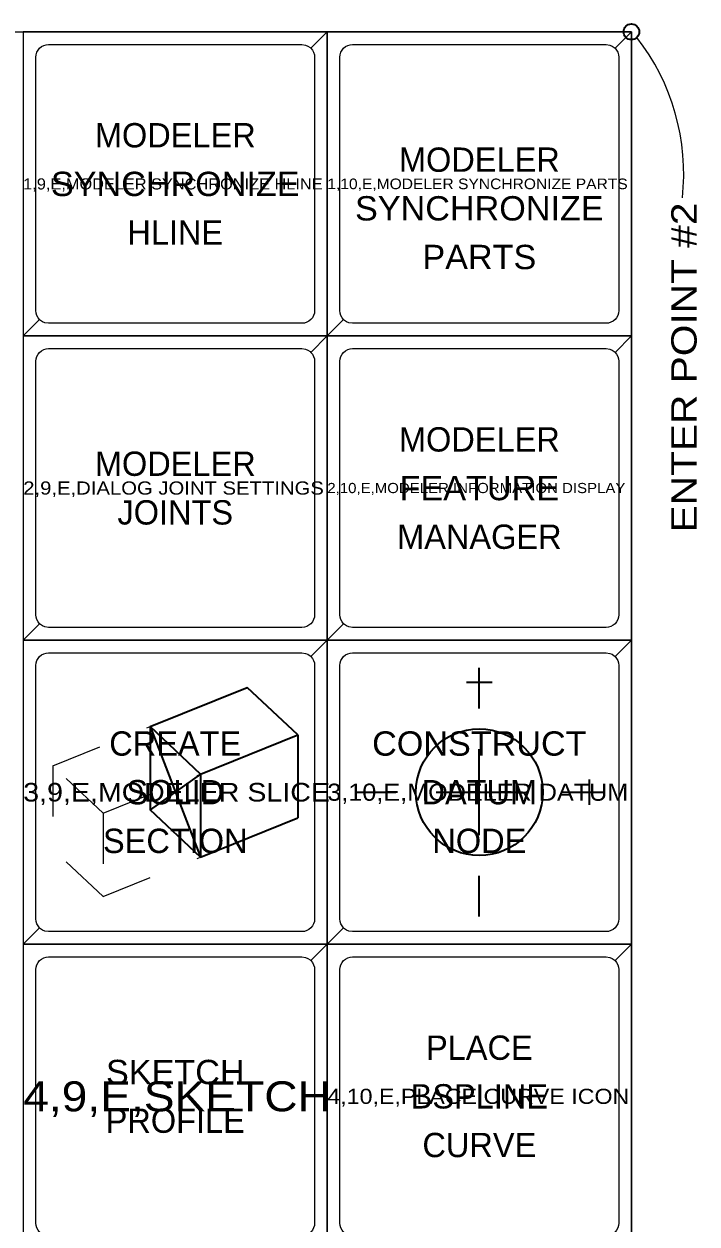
# Model space of a CAD drawing. Extents: x 95909.2 to 95923.3, y 90965 to 90971.2.
# Drawn here: x 95914.588 to 95915.916, y 90968.808 to 90971.176 of the extents above; entities that cross this region are included whole.
import ezdxf
from ezdxf.enums import TextEntityAlignment as Align

# ---------------------------------------------------------------- set-up
doc = ezdxf.new("R2010")
doc.units = 0
doc.header["$LTSCALE"] = 0.019
doc.linetypes.add('MEDIUM_DASHED', pattern=[4.5, 3, -1.5])
for name, color, linetype, lineweight in [('1', 7, 'Continuous', 25), ('10', 7, 'Continuous', 13), ('2', 7, 'Continuous', 25), ('3', 7, 'Continuous', 25), ('4', 7, 'Continuous', 25), ('6', 7, 'Continuous', 13), ('7', 7, 'Continuous', 35)]:
    doc.layers.add(name, color=color, linetype=linetype, lineweight=lineweight)
for name, color, linetype in [('5', 7, 'Continuous'), ('63', 7, 'Continuous'), ('9', 7, 'Continuous')]:
    doc.layers.add(name, color=color, linetype=linetype)

msp = doc.modelspace()

# ---------------------------------------------------------------- linework, layer by layer
at = {"layer": '1'}
for points in [[(95914.5868, 90970.5603), (95915.1868, 90970.5603), (95915.1868, 90971.1603), (95914.5868, 90971.1603)], [(95915.1868, 90970.5603), (95915.7868, 90970.5603), (95915.7868, 90971.1603), (95915.1868, 90971.1603)], [(95914.5868, 90969.9603), (95915.1868, 90969.9603), (95915.1868, 90970.5603), (95914.5868, 90970.5603)], [(95915.1868, 90969.9603), (95915.7868, 90969.9603), (95915.7868, 90970.5603), (95915.1868, 90970.5603)], [(95914.5868, 90969.3603), (95915.1868, 90969.3603), (95915.1868, 90969.9603), (95914.5868, 90969.9603)], [(95915.1868, 90969.3603), (95915.7868, 90969.3603), (95915.7868, 90969.9603), (95915.1868, 90969.9603)], [(95914.5868, 90968.7603), (95915.1868, 90968.7603), (95915.1868, 90969.3603), (95914.5868, 90969.3603)], [(95915.1868, 90968.7603), (95915.7868, 90968.7603), (95915.7868, 90969.3603), (95915.1868, 90969.3603)]]:
    msp.add_lwpolyline(points, close=True, dxfattribs=at)
at = {"layer": '10'}
msp.add_lwpolyline([(95909.7868, 90971.1603), (95915.7868, 90971.1603), (95915.7868, 90966.3603), (95909.7868, 90966.3603)], close=True, dxfattribs=at)
at = {"layer": '2'}
for points in [[(95914.5868, 90970.5603), (95915.1868, 90970.5603), (95915.1868, 90971.1603), (95914.5868, 90971.1603)], [(95915.1868, 90970.5603), (95915.7868, 90970.5603), (95915.7868, 90971.1603), (95915.1868, 90971.1603)], [(95914.5868, 90969.9603), (95915.1868, 90969.9603), (95915.1868, 90970.5603), (95914.5868, 90970.5603)], [(95915.1868, 90969.9603), (95915.7868, 90969.9603), (95915.7868, 90970.5603), (95915.1868, 90970.5603)], [(95914.5868, 90969.3603), (95915.1868, 90969.3603), (95915.1868, 90969.9603), (95914.5868, 90969.9603)], [(95915.1868, 90969.3603), (95915.7868, 90969.3603), (95915.7868, 90969.9603), (95915.1868, 90969.9603)], [(95914.5868, 90968.7603), (95915.1868, 90968.7603), (95915.1868, 90969.3603), (95914.5868, 90969.3603)], [(95915.1868, 90968.7603), (95915.7868, 90968.7603), (95915.7868, 90969.3603), (95915.1868, 90969.3603)]]:
    msp.add_lwpolyline(points, close=True, dxfattribs=at)
at = {"layer": '3'}
for points in [[(95915.1868, 90971.1603), (95914.5868, 90971.1603), (95914.5868, 90970.5603), (95914.6191, 90970.5926), (95914.616, 90970.5964), (95914.6137, 90970.6007), (95914.6123, 90970.6054), (95914.6118, 90970.6103), (95914.6118, 90971.1103), (95914.6123, 90971.1152), (95914.6137, 90971.1199), (95914.616, 90971.1242), (95914.6191, 90971.128), (95914.6191, 90971.128), (95914.6229, 90971.1311), (95914.6272, 90971.1334), (95914.6319, 90971.1348), (95914.6368, 90971.1353), (95915.1368, 90971.1353), (95915.1441, 90971.1342), (95915.1486, 90971.1323), (95915.1527, 90971.1296), (95915.1545, 90971.128)], [(95915.7868, 90971.1603), (95915.1868, 90971.1603), (95915.1868, 90970.5603), (95915.2191, 90970.5926), (95915.216, 90970.5964), (95915.2137, 90970.6007), (95915.2123, 90970.6054), (95915.2118, 90970.6103), (95915.2118, 90971.1103), (95915.2123, 90971.1152), (95915.2137, 90971.1199), (95915.216, 90971.1242), (95915.2191, 90971.128), (95915.2191, 90971.128), (95915.2229, 90971.1311), (95915.2272, 90971.1334), (95915.2319, 90971.1348), (95915.2368, 90971.1353), (95915.7368, 90971.1353), (95915.7441, 90971.1342), (95915.7486, 90971.1323), (95915.7527, 90971.1296), (95915.7545, 90971.128)], [(95915.1868, 90970.5603), (95914.5868, 90970.5603), (95914.5868, 90969.9603), (95914.6191, 90969.9926), (95914.616, 90969.9964), (95914.6137, 90970.0007), (95914.6123, 90970.0054), (95914.6118, 90970.0103), (95914.6118, 90970.5103), (95914.6123, 90970.5152), (95914.6137, 90970.5199), (95914.616, 90970.5242), (95914.6191, 90970.528), (95914.6191, 90970.528), (95914.6229, 90970.5311), (95914.6272, 90970.5334), (95914.6319, 90970.5348), (95914.6368, 90970.5353), (95915.1368, 90970.5353), (95915.1441, 90970.5342), (95915.1486, 90970.5323), (95915.1527, 90970.5296), (95915.1545, 90970.528)], [(95915.7868, 90970.5603), (95915.1868, 90970.5603), (95915.1868, 90969.9603), (95915.2191, 90969.9926), (95915.216, 90969.9964), (95915.2137, 90970.0007), (95915.2123, 90970.0054), (95915.2118, 90970.0103), (95915.2118, 90970.5103), (95915.2123, 90970.5152), (95915.2137, 90970.5199), (95915.216, 90970.5242), (95915.2191, 90970.528), (95915.2191, 90970.528), (95915.2229, 90970.5311), (95915.2272, 90970.5334), (95915.2319, 90970.5348), (95915.2368, 90970.5353), (95915.7368, 90970.5353), (95915.7441, 90970.5342), (95915.7486, 90970.5323), (95915.7527, 90970.5296), (95915.7545, 90970.528)], [(95915.1868, 90969.9603), (95914.5868, 90969.9603), (95914.5868, 90969.3603), (95914.6191, 90969.3926), (95914.616, 90969.3964), (95914.6137, 90969.4007), (95914.6123, 90969.4054), (95914.6118, 90969.4103), (95914.6118, 90969.9103), (95914.6123, 90969.9152), (95914.6137, 90969.9199), (95914.616, 90969.9242), (95914.6191, 90969.928), (95914.6191, 90969.928), (95914.6229, 90969.9311), (95914.6272, 90969.9334), (95914.6319, 90969.9348), (95914.6368, 90969.9353), (95915.1368, 90969.9353), (95915.1441, 90969.9342), (95915.1486, 90969.9323), (95915.1527, 90969.9296), (95915.1545, 90969.928)], [(95915.7868, 90969.9603), (95915.1868, 90969.9603), (95915.1868, 90969.3603), (95915.2191, 90969.3926), (95915.216, 90969.3964), (95915.2137, 90969.4007), (95915.2123, 90969.4054), (95915.2118, 90969.4103), (95915.2118, 90969.9103), (95915.2123, 90969.9152), (95915.2137, 90969.9199), (95915.216, 90969.9242), (95915.2191, 90969.928), (95915.2191, 90969.928), (95915.2229, 90969.9311), (95915.2272, 90969.9334), (95915.2319, 90969.9348), (95915.2368, 90969.9353), (95915.7368, 90969.9353), (95915.7441, 90969.9342), (95915.7486, 90969.9323), (95915.7527, 90969.9296), (95915.7545, 90969.928)], [(95915.1868, 90969.3603), (95914.5868, 90969.3603), (95914.5868, 90968.7603), (95914.6191, 90968.7926), (95914.616, 90968.7964), (95914.6137, 90968.8007), (95914.6123, 90968.8054), (95914.6118, 90968.8103), (95914.6118, 90969.3103), (95914.6123, 90969.3152), (95914.6137, 90969.3199), (95914.616, 90969.3242), (95914.6191, 90969.328), (95914.6191, 90969.328), (95914.6229, 90969.3311), (95914.6272, 90969.3334), (95914.6319, 90969.3348), (95914.6368, 90969.3353), (95915.1368, 90969.3353), (95915.1441, 90969.3342), (95915.1486, 90969.3323), (95915.1527, 90969.3296), (95915.1545, 90969.328)], [(95915.7868, 90969.3603), (95915.1868, 90969.3603), (95915.1868, 90968.7603), (95915.2191, 90968.7926), (95915.216, 90968.7964), (95915.2137, 90968.8007), (95915.2123, 90968.8054), (95915.2118, 90968.8103), (95915.2118, 90969.3103), (95915.2123, 90969.3152), (95915.2137, 90969.3199), (95915.216, 90969.3242), (95915.2191, 90969.328), (95915.2191, 90969.328), (95915.2229, 90969.3311), (95915.2272, 90969.3334), (95915.2319, 90969.3348), (95915.2368, 90969.3353), (95915.7368, 90969.3353), (95915.7441, 90969.3342), (95915.7486, 90969.3323), (95915.7527, 90969.3296), (95915.7545, 90969.328)]]:
    msp.add_lwpolyline(points, close=True, dxfattribs=at)
at = {"layer": '4'}
for points in [[(95914.5868, 90970.5603), (95915.1868, 90970.5603), (95915.1868, 90971.1603), (95915.1545, 90971.128), (95915.1576, 90971.1242), (95915.1599, 90971.1199), (95915.1613, 90971.1152), (95915.1618, 90971.1103), (95915.1618, 90970.6103), (95915.1613, 90970.6054), (95915.1599, 90970.6007), (95915.1576, 90970.5964), (95915.1545, 90970.5926), (95915.1545, 90970.5926), (95915.1507, 90970.5895), (95915.1464, 90970.5872), (95915.1417, 90970.5858), (95915.1368, 90970.5853), (95914.6368, 90970.5853), (95914.6295, 90970.5864), (95914.625, 90970.5883), (95914.6209, 90970.591), (95914.6191, 90970.5926)], [(95915.1868, 90970.5603), (95915.7868, 90970.5603), (95915.7868, 90971.1603), (95915.7545, 90971.128), (95915.7576, 90971.1242), (95915.7599, 90971.1199), (95915.7613, 90971.1152), (95915.7618, 90971.1103), (95915.7618, 90970.6103), (95915.7613, 90970.6054), (95915.7599, 90970.6007), (95915.7576, 90970.5964), (95915.7545, 90970.5926), (95915.7545, 90970.5926), (95915.7507, 90970.5895), (95915.7464, 90970.5872), (95915.7417, 90970.5858), (95915.7368, 90970.5853), (95915.2368, 90970.5853), (95915.2295, 90970.5864), (95915.225, 90970.5883), (95915.2209, 90970.591), (95915.2191, 90970.5926)], [(95914.5868, 90969.9603), (95915.1868, 90969.9603), (95915.1868, 90970.5603), (95915.1545, 90970.528), (95915.1576, 90970.5242), (95915.1599, 90970.5199), (95915.1613, 90970.5152), (95915.1618, 90970.5103), (95915.1618, 90970.0103), (95915.1613, 90970.0054), (95915.1599, 90970.0007), (95915.1576, 90969.9964), (95915.1545, 90969.9926), (95915.1545, 90969.9926), (95915.1507, 90969.9895), (95915.1464, 90969.9872), (95915.1417, 90969.9858), (95915.1368, 90969.9853), (95914.6368, 90969.9853), (95914.6295, 90969.9864), (95914.625, 90969.9883), (95914.6209, 90969.991), (95914.6191, 90969.9926)], [(95915.1868, 90969.9603), (95915.7868, 90969.9603), (95915.7868, 90970.5603), (95915.7545, 90970.528), (95915.7576, 90970.5242), (95915.7599, 90970.5199), (95915.7613, 90970.5152), (95915.7618, 90970.5103), (95915.7618, 90970.0103), (95915.7613, 90970.0054), (95915.7599, 90970.0007), (95915.7576, 90969.9964), (95915.7545, 90969.9926), (95915.7545, 90969.9926), (95915.7507, 90969.9895), (95915.7464, 90969.9872), (95915.7417, 90969.9858), (95915.7368, 90969.9853), (95915.2368, 90969.9853), (95915.2295, 90969.9864), (95915.225, 90969.9883), (95915.2209, 90969.991), (95915.2191, 90969.9926)], [(95914.5868, 90969.3603), (95915.1868, 90969.3603), (95915.1868, 90969.9603), (95915.1545, 90969.928), (95915.1576, 90969.9242), (95915.1599, 90969.9199), (95915.1613, 90969.9152), (95915.1618, 90969.9103), (95915.1618, 90969.4103), (95915.1613, 90969.4054), (95915.1599, 90969.4007), (95915.1576, 90969.3964), (95915.1545, 90969.3926), (95915.1545, 90969.3926), (95915.1507, 90969.3895), (95915.1464, 90969.3872), (95915.1417, 90969.3858), (95915.1368, 90969.3853), (95914.6368, 90969.3853), (95914.6295, 90969.3864), (95914.625, 90969.3883), (95914.6209, 90969.391), (95914.6191, 90969.3926)], [(95915.1868, 90969.3603), (95915.7868, 90969.3603), (95915.7868, 90969.9603), (95915.7545, 90969.928), (95915.7576, 90969.9242), (95915.7599, 90969.9199), (95915.7613, 90969.9152), (95915.7618, 90969.9103), (95915.7618, 90969.4103), (95915.7613, 90969.4054), (95915.7599, 90969.4007), (95915.7576, 90969.3964), (95915.7545, 90969.3926), (95915.7545, 90969.3926), (95915.7507, 90969.3895), (95915.7464, 90969.3872), (95915.7417, 90969.3858), (95915.7368, 90969.3853), (95915.2368, 90969.3853), (95915.2295, 90969.3864), (95915.225, 90969.3883), (95915.2209, 90969.391), (95915.2191, 90969.3926)], [(95914.5868, 90968.7603), (95915.1868, 90968.7603), (95915.1868, 90969.3603), (95915.1545, 90969.328), (95915.1576, 90969.3242), (95915.1599, 90969.3199), (95915.1613, 90969.3152), (95915.1618, 90969.3103), (95915.1618, 90968.8103), (95915.1613, 90968.8054), (95915.1599, 90968.8007), (95915.1576, 90968.7964), (95915.1545, 90968.7926), (95915.1545, 90968.7926), (95915.1507, 90968.7895), (95915.1464, 90968.7872), (95915.1417, 90968.7858), (95915.1368, 90968.7853), (95914.6368, 90968.7853), (95914.6295, 90968.7864), (95914.625, 90968.7883), (95914.6209, 90968.791), (95914.6191, 90968.7926)], [(95915.1868, 90968.7603), (95915.7868, 90968.7603), (95915.7868, 90969.3603), (95915.7545, 90969.328), (95915.7576, 90969.3242), (95915.7599, 90969.3199), (95915.7613, 90969.3152), (95915.7618, 90969.3103), (95915.7618, 90968.8103), (95915.7613, 90968.8054), (95915.7599, 90968.8007), (95915.7576, 90968.7964), (95915.7545, 90968.7926), (95915.7545, 90968.7926), (95915.7507, 90968.7895), (95915.7464, 90968.7872), (95915.7417, 90968.7858), (95915.7368, 90968.7853), (95915.2368, 90968.7853), (95915.2295, 90968.7864), (95915.225, 90968.7883), (95915.2209, 90968.791), (95915.2191, 90968.7926)]]:
    msp.add_lwpolyline(points, close=True, dxfattribs=at)
at = {"layer": '6', "lineweight": 35}
for p, q in [((95915.4868, 90969.8253), (95915.4868, 90969.9053)), ((95915.4618, 90969.8772), (95915.5118, 90969.8772)), ((95914.837, 90969.7897), (95915.029, 90969.8671)), ((95915.1285, 90969.7736), (95915.029, 90969.8671)), ((95914.9365, 90969.6961), (95914.837, 90969.7897)), ((95914.837, 90969.7897), (95914.837, 90969.6254)), ((95914.837, 90969.7897), (95914.9365, 90969.5319)), ((95914.9365, 90969.6961), (95915.1285, 90969.7736)), ((95915.1285, 90969.7736), (95915.1285, 90969.6094)), ((95915.4868, 90969.5753), (95915.4868, 90969.7453)), ((95914.9365, 90969.6961), (95914.837, 90969.6254)), ((95914.9365, 90969.6961), (95914.9365, 90969.5319)), ((95915.7037, 90969.6853), (95915.7037, 90969.6353)), ((95915.2418, 90969.6603), (95915.3218, 90969.6603)), ((95915.4018, 90969.6603), (95915.5718, 90969.6603)), ((95915.6518, 90969.6603), (95915.7318, 90969.6603)), ((95914.9365, 90969.5319), (95914.837, 90969.6254)), ((95914.9365, 90969.5319), (95915.1285, 90969.6094)), ((95915.4868, 90969.4153), (95915.4868, 90969.4953))]:
    msp.add_line(p, q, dxfattribs=at)
at = {"layer": '6', "linetype": 'MEDIUM_DASHED'}
for p, q in [((95914.645, 90969.7121), (95914.837, 90969.7897)), ((95914.7445, 90969.6187), (95914.645, 90969.7121)), ((95914.645, 90969.7121), (95914.645, 90969.548)), ((95914.7445, 90969.6187), (95914.9365, 90969.6961)), ((95914.7445, 90969.6187), (95914.7445, 90969.4544)), ((95914.7445, 90969.4544), (95914.645, 90969.548)), ((95914.7445, 90969.4544), (95914.9365, 90969.5319))]:
    msp.add_line(p, q, dxfattribs=at)
at = {"layer": '6', "lineweight": 35}
msp.add_circle((95915.4868, 90969.6603), 0.125, dxfattribs=at)
at = {"layer": '7'}
msp.add_circle((95915.7868, 90971.1603), 0.01543, dxfattribs=at)
at = {"layer": '7', "lineweight": 25}
msp.add_arc((95915.45152, 90970.88013), 0.43857, 353.76514, 37.87715, dxfattribs=at)

# ---------------------------------------------------------------- texts
at = {"layer": '5'}
for s, p in [('CREATE', (95914.88675, 90969.7323)), ('SOLID', (95914.8868, 90969.6363)), ('DATUM', (95915.4868, 90969.6363)), ('SECTION', (95914.88685, 90969.5403)), ('NODE', (95915.4868, 90969.5403))]:
    msp.add_text(s, height=0.048, dxfattribs=at).set_placement(p, align=Align.CENTER)
at = {"layer": '5', "width": 1.05}
msp.add_text('CONSTRUCT', height=0.048, dxfattribs=at).set_placement((95915.4868, 90969.7323), align=Align.CENTER)
at = {"layer": '63'}
for s, height, width, p in [('1,9,E,MODELER SYNCHRONIZE HLINE', 0.0219, 1.1, (95914.5868, 90970.8493)), ('1,10,E,MODELER SYNCHRONIZE PARTS', 0.0209, 1.1, (95915.1868, 90970.8499)), ('2,9,E,DIALOG JOINT SETTINGS', 0.026, 1.15, (95914.5868, 90970.2473)), ('2,10,E,MODELER INFORMATION DISPLAY', 0.0201, 1.1, (95915.1868, 90970.2503)), ('3,9,E,MODELER SLICE', 0.0367, 1.15, (95914.5868, 90969.6419)), ('3,10,E,MODELER DATUM', 0.0338, 1.1, (95915.1868, 90969.6434)), ('4,9,E,SKETCH', 0.0592, 1.15, (95914.5868, 90969.0307)), ('4,10,E,PLACE CURVE ICON', 0.0298, 1.15, (95915.1868, 90969.0454))]:
    msp.add_text(s, height=height, dxfattribs=dict(at, width=width)).set_placement(p)
at = {"layer": '7', "width": 1.2}
msp.add_text('ENTER POINT #2', height=0.05, rotation=90, dxfattribs=at).set_placement((95915.9156, 90970.4981), align=Align.CENTER)
at = {"layer": '9'}
for s, p in [('MODELER', (95914.88685, 90970.9323)), ('MODELER', (95915.48685, 90970.8841)), ('HLINE', (95914.8868, 90970.7403)), ('MODELER', (95915.48685, 90970.3323)), ('MODELER', (95914.88685, 90970.2843)), ('JOINTS', (95914.8868, 90970.1883)), ('MANAGER', (95915.48685, 90970.1403)), ('PLACE', (95915.48685, 90969.1323)), ('BSPLINE', (95915.4868, 90969.0363)), ('PROFILE', (95914.8868, 90968.9883)), ('CURVE', (95915.4868, 90968.9403))]:
    msp.add_text(s, height=0.048, dxfattribs=at).set_placement(p, align=Align.CENTER)
at = {"layer": '9', "width": 1.05}
for s, p in [('SYNCHRONIZE', (95914.8868, 90970.8363)), ('SYNCHRONIZE', (95915.4868, 90970.7881)), ('PARTS', (95915.4868, 90970.6921)), ('FEATURE', (95915.4868, 90970.2363)), ('SKETCH', (95914.88685, 90969.0843))]:
    msp.add_text(s, height=0.048, dxfattribs=at).set_placement(p, align=Align.CENTER)

doc.saveas('drawing.dxf')
